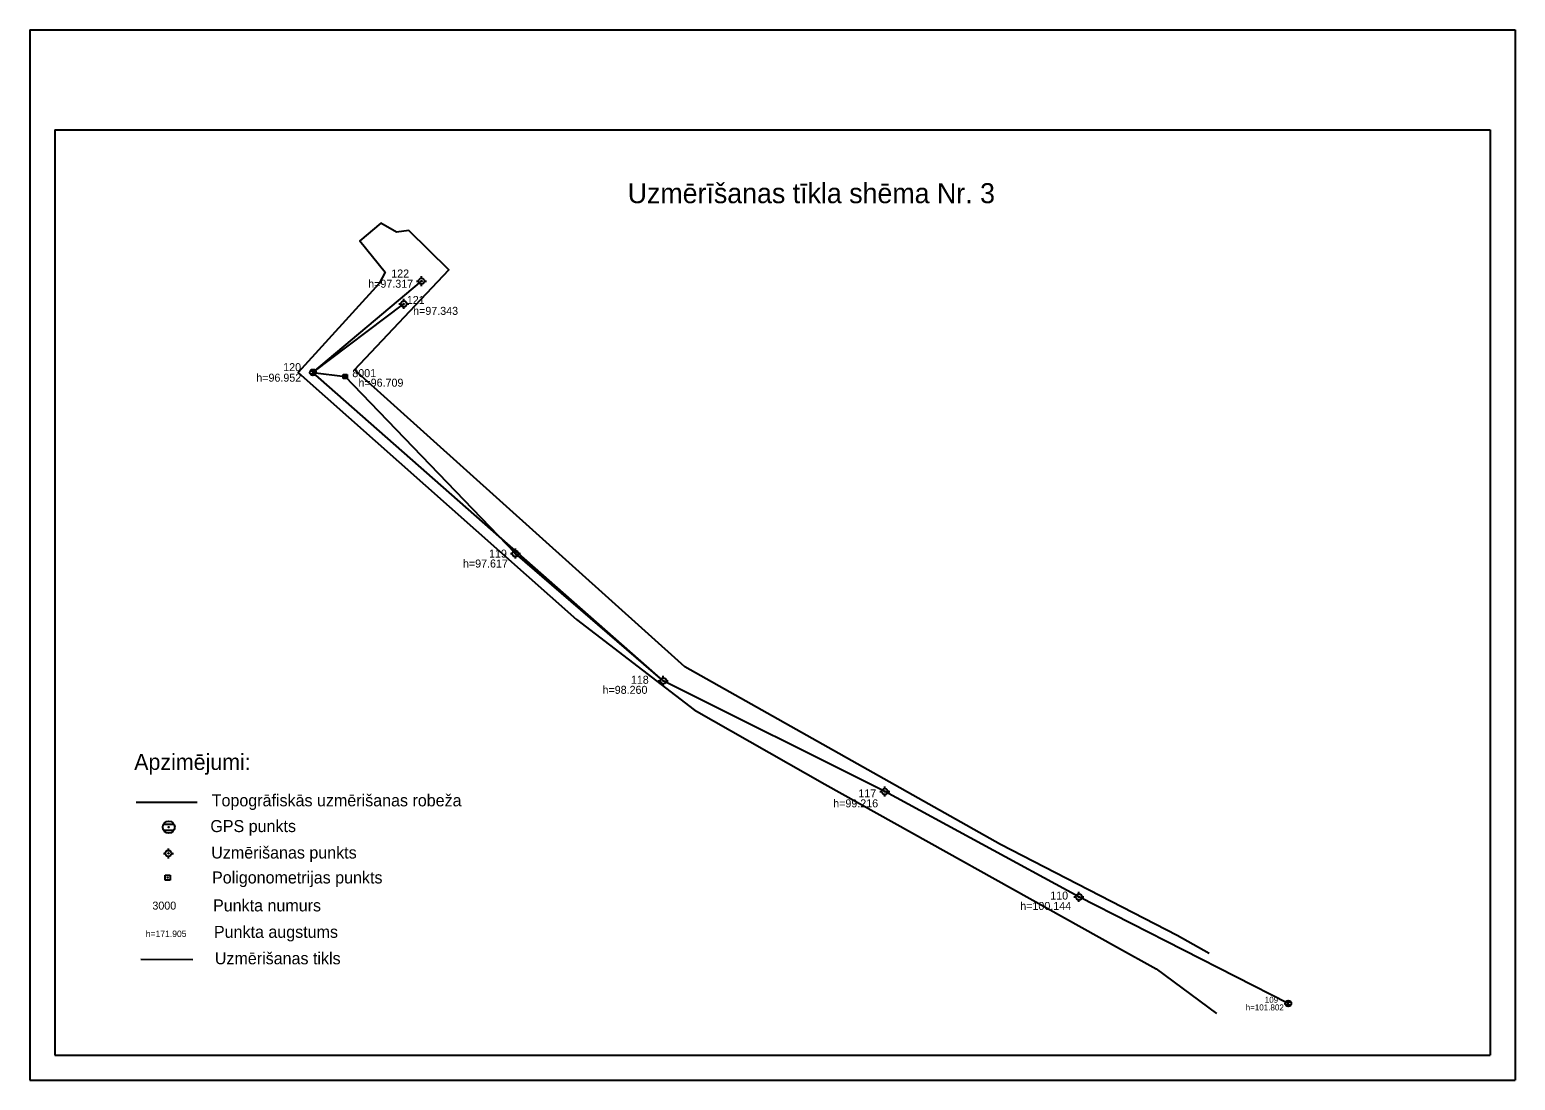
# Model space of a CAD drawing. Extents: x 614915 to 615767, y 262115 to 264410.
# Drawn here: x 615007 to 615750, y 263885 to 264410 of the extents above; entities that cross this region are included whole.
import ezdxf

# ---------------------------------------------------------------- set-up
doc = ezdxf.new("R2010")
doc.units = 0
for name, color, linetype in [('Level 19', 7, 'Continuous'), ('Level 25', 7, 'Continuous'), ('Level 63', 7, 'Continuous')]:
    doc.layers.add(name, color=color, linetype=linetype)

msp = doc.modelspace()

# ---------------------------------------------------------------- linework, layer by layer
at = {"layer": 'Level 19'}
for p, q in [((615203.3, 264285.71), (615203.3, 264286.71)), ((615149.04, 264238.62), (615203.3, 264284.21)), ((615200.8, 264284.21), (615201.8, 264284.21)), ((615203.3, 264281.71), (615203.3, 264282.71)), ((615204.8, 264284.21), (615205.8, 264284.21)), ((615149.04, 264238.62), (615194.49, 264272.8)), ((615191.99, 264272.8), (615192.99, 264272.8)), ((615194.49, 264274.31), (615194.49, 264275.31)), ((615194.49, 264270.31), (615194.49, 264271.31)), ((615195.99, 264272.8), (615196.99, 264272.8)), ((615147.74, 264239.37), (615150.34, 264239.37)), ((615147.74, 264237.87), (615150.34, 264237.87)), ((615324.17, 264084.5), (615149.04, 264238.62)), ((615149.04, 264238.62), (615165.21, 264236.61)), ((615164.21, 264237.61), (615166.21, 264237.61)), ((615164.21, 264235.61), (615164.21, 264237.61)), ((615166.21, 264235.61), (615164.21, 264235.61)), ((615250.22, 264148.03), (615165.21, 264236.61)), ((615166.21, 264237.61), (615166.21, 264235.61)), ((615247.72, 264148.03), (615248.72, 264148.03)), ((615250.22, 264149.53), (615250.22, 264150.53)), ((615324.17, 264084.5), (615250.22, 264148.03)), ((615250.22, 264145.53), (615250.22, 264146.53)), ((615251.72, 264148.03), (615252.72, 264148.03)), ((615324.17, 264086), (615324.17, 264087)), ((615321.67, 264084.5), (615322.67, 264084.5)), ((615434.89, 264029.12), (615324.17, 264084.5)), ((615324.17, 264082), (615324.17, 264083)), ((615325.67, 264084.5), (615326.67, 264084.5)), ((615432.39, 264029.12), (615433.39, 264029.12)), ((615434.89, 264030.62), (615434.89, 264031.62)), ((615531.9, 263976.49), (615434.89, 264029.12)), ((615434.89, 264026.62), (615434.89, 264027.62)), ((615436.39, 264029.12), (615437.39, 264029.12)), ((615074.39, 264012.83), (615079.59, 264012.83)), ((615074.39, 264009.83), (615079.59, 264009.83)), ((615074.32, 263998.25), (615075.32, 263998.25)), ((615076.82, 263999.75), (615076.82, 264000.75)), ((615076.82, 263995.75), (615076.82, 263996.75)), ((615078.32, 263998.25), (615079.32, 263998.25)), ((615075.26, 263987.28), (615077.66, 263987.28)), ((615075.26, 263984.88), (615075.26, 263987.28)), ((615077.66, 263984.88), (615075.26, 263984.88)), ((615077.66, 263987.28), (615077.66, 263984.88)), ((615529.4, 263976.49), (615530.4, 263976.49)), ((615531.9, 263977.99), (615531.9, 263978.99)), ((615636.56, 263923.23), (615531.9, 263976.49)), ((615531.9, 263973.99), (615531.9, 263974.99)), ((615533.4, 263976.49), (615534.4, 263976.49)), ((615088.95, 263945.08), (615062.98, 263945.14)), ((615635.26, 263923.98), (615637.86, 263923.98)), ((615635.26, 263922.48), (615637.86, 263922.48))]:
    msp.add_line(p, q, dxfattribs=at)
for centre, radius in [((615203.3, 264284.21), 1.5), ((615203.3, 264284.21), 0.2), ((615194.49, 264272.8), 1.5), ((615194.49, 264272.8), 0.2), ((615149.04, 264238.62), 1.5), ((615149.04, 264238.62), 0.08), ((615165.21, 264236.61), 0.1), ((615250.22, 264148.03), 1.5), ((615250.22, 264148.03), 0.2), ((615324.17, 264084.5), 1.5), ((615324.17, 264084.5), 0.2), ((615434.89, 264029.12), 1.5), ((615434.89, 264029.12), 0.2), ((615076.99, 264011.33), 3), ((615076.99, 264011.33), 0.16), ((615076.82, 263998.25), 1.5), ((615076.82, 263998.25), 0.2), ((615076.46, 263986.08), 0.12), ((615531.9, 263976.49), 1.5), ((615531.9, 263976.49), 0.2), ((615636.56, 263923.23), 1.5), ((615636.56, 263923.23), 0.08)]:
    msp.add_circle(centre, radius, dxfattribs=at)
at = {"layer": 'Level 25'}
msp.add_line((615060.71, 264023.89), (615091.27, 264023.89), dxfattribs=at)
msp.add_lwpolyline([(615597.04, 263948.14), (615581.01, 263957.13), (615492.73, 264002.69), (615334.88, 264091.49), (615169.8, 264239.8), (615216.95, 264289.91), (615196.96, 264309.43), (615190.87, 264308.68), (615182.99, 264313.15), (615172.44, 264304.34), (615185.08, 264288.72), (615182.2, 264283.02), (615141.7, 264238.63), (615280.86, 264115.06), (615339.64, 264070.01), (615404.96, 264032.79), (615550.73, 263951.61), (615570.52, 263940.55), (615600.71, 263918.27)], dxfattribs=at)
at = {"layer": 'Level 63'}
for p, q in [((615007.49, 264409.85), (615749.99, 264409.85)), ((615007.49, 264409.85), (615007.49, 263884.85)), ((615749.99, 264409.85), (615749.99, 263884.85)), ((615019.99, 264359.85), (615737.49, 264359.85)), ((615019.99, 264359.85), (615019.99, 263897.35)), ((615737.49, 264359.85), (615737.49, 263897.35)), ((615019.99, 263897.35), (615737.49, 263897.35)), ((615007.49, 263884.85), (615749.99, 263884.85))]:
    msp.add_line(p, q, dxfattribs=at)

# ---------------------------------------------------------------- texts
at = {"layer": 'Level 19'}
for s, height, p in [(' 122', 4, (615186.72, 264286.01)), ('h=97.317', 4, (615176.67, 264280.91)), (' 121', 4, (615194.49, 264272.8)), ('h=97.343', 4, (615199.14, 264267.35)), (' 120', 4, (615132.7, 264239.23)), ('h=96.952', 4, (615120.74, 264233.96)), (' 8001', 4, (615167.24, 264236.23)), ('h=96.709', 4, (615171.81, 264231.45)), ('h=97.617', 4, (615224.03, 264141.09)), (' 119', 4, (615235.58, 264146.06)), (' 118', 4, (615306.47, 264083)), ('h=98.260', 4, (615293.79, 264077.97)), (' 117', 4, (615420.18, 264026.24)), ('h=99.216', 4, (615409.08, 264021.24)), (' 3000', 4, (615067.33, 263970.14)), ('h=100.144', 4, (615502.57, 263969.96)), (' 110', 4, (615516.07, 263975.14)), (' h=171.905', 3.2, (615064.33, 263956.47)), ('h=101.802', 3, (615615.23, 263919.76)), (' 109', 3, (615623.67, 263923.57))]:
    msp.add_text(s, height=height, dxfattribs=at).set_placement(p)
at = {"layer": 'Level 63'}
for s, height, p in [('Uzmērīšanas tīkla shēma Nr. 3', 10, (615306.37, 264323.16)), ('Apzimējumi:', 8, (615059.72, 264039.94)), ('Topogrāfiskās uzmērišanas robeža', 6, (615098.46, 264021.74)), ('GPS punkts', 6, (615097.78, 264008.88)), ('Uzmērišanas punkts', 6, (615098.23, 263995.67)), ('Poligonometrijas punkts', 6, (615098.63, 263983.2)), ('Punkta numurs', 6, (615099.13, 263969.24)), ('Punkta augstums', 6, (615099.58, 263956.03)), ('Uzmērišanas tikls', 6, (615100.02, 263942.81))]:
    msp.add_text(s, height=height, dxfattribs=at).set_placement(p)

doc.saveas('drawing.dxf')
